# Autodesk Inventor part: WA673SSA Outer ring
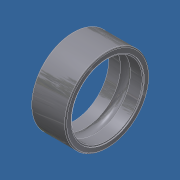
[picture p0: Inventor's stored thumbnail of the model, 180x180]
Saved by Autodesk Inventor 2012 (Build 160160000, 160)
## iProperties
Category: PARTsolutions
Created: 2011-07
Part Number: WA673SSA Outer ring
Catalog Web Link: www.cadenas.de
Description: Six types or - Metric system sizes
Document SubType Name: Modeling
Designer: PARTsolutions
Density: 1 g/cm^3
Material: Par défaut
NB: WA673SSA Outer ring
NN: Six types or
NT: Metric system sizes
NBSYN: $ORDER. Outer ring
LINA: WA673SSA Outer ring
SD: 3.0
D: 6
B: 2.0
R: 0.08
ORDER: WA673SSA
CR: 242
COR: 94
CRF: 25
CORF: 9,5
LSG: 60 000
LSO: 71 000
MASS: 0.20
D1: 7.2
D2: 7.2
C1: 0.6
C2: 0.6
ORDER1: 673
WSS: WA673SSA
WDS: SSA
UTWF: FL673
FORSS: FLWA673SA
FORDS: SSA
DA1: 3,6
DA2: 4,1
DA: 5,4
RAS: 0,08
MASS1: 0.26
B1: 2.5
VERS: 3
X: 1.500
N: 9
O: 14.130
RB: 0.444
KT: DUMMY
SUPPLIER: NTN
ARTICLENO: WA673SSA Outer ring
BOMINFO: WA673SSA Outer ring
CREATOR: CADENAS GmbH
PSOL_IDENT_0: {\\10.0.0.251\ps_data\23d-libs\ntn\ball_roller_bearings\miniature_extra_small_bb\metric_system_sizes
PSOL_IDENT_1: \mss_or.prj},189 {VTYP=3D},{NB=WA673SSA Outer ring},{LINA=WA673SSA Outer ring},{NN=Six types or},{DA
PSOL_IDENT_2: TE=11.12.2007 08:48:24},{GEOMDATE=02.04.2007 00:00:00},{VERSION=},{LINEID=12590},{LINESUBID=-1},{WBV
PSOL_IDENT_3: AR=}  {NB=WA673SSA Outer ring},{LINA=WA673SSA Outer ring},{KT=DUMMY},{IDNR=},{SD=3.0},{D=6},{B=2.0},
PSOL_IDENT_4: {R=0.08},{ORDER=WA673SSA},{CR=242},{COR=94},{CRF=25},{CORF=9,5},{LSG=60 000},{LSO=71 000},{MASS=0.20
PSOL_IDENT_5: },{D1=7.2},{D2=7.2},{C1=0.6},{C2=0.6},{ORDER1=673},{WSS=WA673SSA},{WDS=SSA},{UTWF=FL673},{FORSS=FLWA
PSOL_IDENT_6: 673SA},{FORDS=SSA},{DA1=3,6},{DA2=4,1},{DA=5,4},{RAS=0,08},{MASS1=0.26},{B1=2.5},{VERS=3},{X=1.5},{N
PSOL_IDENT_7: =9},{O=14.13},{RB=0.444}
Title: WA673SSA Outer ring
Author: Cadenas PARTsolutions
Comments: Metric system sizes
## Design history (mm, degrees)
sketch "Sketch_3"
  geometry: L1 (2.5, 0)-(0, 0); L2 (0, 2.92)-(0, 2.616); L3 (0, 2.616)-(0.056, 2.616); L4 (0.056, 2.616)-(0.056, 2.52); L5 (0.056, 2.52)-(0.898, 2.52); L6 (1.602, 2.52)-(2.444, 2.52); L7 (2.444, 2.52)-(2.444, 2.616); L8 (2.444, 2.616)-(2.5, 2.616); L9 (2.5, 2.616)-(2.5, 2.92); L10 (2.42, 3)-(0.08, 3); A1 r 0.444 centre (1.25, 2.25) between (1.602, 2.52) and (0.898, 2.52); A2 r 0.08 centre (2.42, 2.92) between (2.5, 2.92) and (2.42, 3); A3 r 0.08 centre (0.08, 2.92) between (0.08, 3) and (0, 2.92)
  constraints: 20 end point, 6 point on circle, 3 centre point
revolve "Revolution1" sketch "Sketch_3" stored, may be unused: angle "d0" = 360 deg
node "mss_or_XY"
node "mss_or_YZ"
node "mss_or_ZX"
node "mss_or_X"
node "mss_or_Y"
node "mss_or_Z"
node "mss_or_Center"
node "mss_or11_XY"
node "mss_or11_YZ"
node "mss_or11_ZX"
node "mss_or11_X"
node "mss_or11_Y"
node "mss_or11_Z"
node "mss_or11_Center"
node "mss_or2_9_XY"
node "mss_or2_9_YZ"
node "mss_or2_9_ZX"
node "mss_or2_9_X"
node "mss_or2_9_Y"
node "mss_or2_9_Z"
node "mss_or2_9_Center"
node "mss_or2_8_XY"
node "mss_or2_8_YZ"
node "mss_or2_8_ZX"
node "mss_or2_8_X"
node "mss_or2_8_Y"
node "mss_or2_8_Z"
node "mss_or2_8_Center"
node "mss_or2_1_XY"
node "mss_or2_1_YZ"
node "mss_or2_1_ZX"
node "mss_or2_1_X"
node "mss_or2_1_Y"
node "mss_or2_1_Z"
node "mss_or2_1_Center"
node "mss_or2_3_XY"
node "mss_or2_3_YZ"
node "mss_or2_3_ZX"
node "mss_or2_3_X"
node "mss_or2_3_Y"
node "mss_or2_3_Z"
node "mss_or2_3_Center"
node "mss_or2_2_XY"
node "mss_or2_2_YZ"
node "mss_or2_2_ZX"
node "mss_or2_2_X"
node "mss_or2_2_Y"
node "mss_or2_2_Z"
node "mss_or2_2_Center"
node "mss_or2_5_XY"
node "mss_or2_5_YZ"
node "mss_or2_5_ZX"
node "mss_or2_5_X"
node "mss_or2_5_Y"
node "mss_or2_5_Z"
node "mss_or2_5_Center"
node "mss_or2_4_XY"
node "mss_or2_4_YZ"
node "mss_or2_4_ZX"
node "mss_or2_4_X"
node "mss_or2_4_Y"
node "mss_or2_4_Z"
node "mss_or2_4_Center"
node "mss_or2_7_XY"
node "mss_or2_7_YZ"
node "mss_or2_7_ZX"
node "mss_or2_7_X"
node "mss_or2_7_Y"
node "mss_or2_7_Z"
node "mss_or2_7_Center"
node "mss_or2_6_XY"
node "mss_or2_6_YZ"
node "mss_or2_6_ZX"
node "mss_or2_6_X"
node "mss_or2_6_Y"
node "mss_or2_6_Z"
node "mss_or2_6_Center"
node "mss_or21_9_XY"
node "mss_or21_9_YZ"
node "mss_or21_9_ZX"
node "mss_or21_9_X"
node "mss_or21_9_Y"
node "mss_or21_9_Z"
node "mss_or21_9_Center"
node "mss_or21_8_XY"
node "mss_or21_8_YZ"
node "mss_or21_8_ZX"
node "mss_or21_8_X"
node "mss_or21_8_Y"
node "mss_or21_8_Z"
node "mss_or21_8_Center"
node "mss_or21_3_XY"
node "mss_or21_3_YZ"
node "mss_or21_3_ZX"
node "mss_or21_3_X"
node "mss_or21_3_Y"
node "mss_or21_3_Z"
node "mss_or21_3_Center"
node "mss_or21_2_XY"
node "mss_or21_2_YZ"
node "mss_or21_2_ZX"
node "mss_or21_2_X"
node "mss_or21_2_Y"
node "mss_or21_2_Z"
node "mss_or21_2_Center"
node "mss_or21_1_XY"
node "mss_or21_1_YZ"
node "mss_or21_1_ZX"
node "mss_or21_1_X"
node "mss_or21_1_Y"
node "mss_or21_1_Z"
node "mss_or21_1_Center"
node "mss_or21_7_XY"
node "mss_or21_7_YZ"
node "mss_or21_7_ZX"
node "mss_or21_7_X"
node "mss_or21_7_Y"
node "mss_or21_7_Z"
node "mss_or21_7_Center"
node "mss_or21_6_XY"
node "mss_or21_6_YZ"
node "mss_or21_6_ZX"
node "mss_or21_6_X"
node "mss_or21_6_Y"
node "mss_or21_6_Z"
node "mss_or21_6_Center"
node "mss_or21_5_XY"
node "mss_or21_5_YZ"
node "mss_or21_5_ZX"
node "mss_or21_5_X"
node "mss_or21_5_Y"
node "mss_or21_5_Z"
node "mss_or21_5_Center"
node "mss_or21_4_XY"
node "mss_or21_4_YZ"
node "mss_or21_4_ZX"
node "mss_or21_4_X"
node "mss_or21_4_Y"
node "mss_or21_4_Z"
node "mss_or21_4_Center"
node "Solide1"
node "Corps solides"
node "Corps surfaciques"
